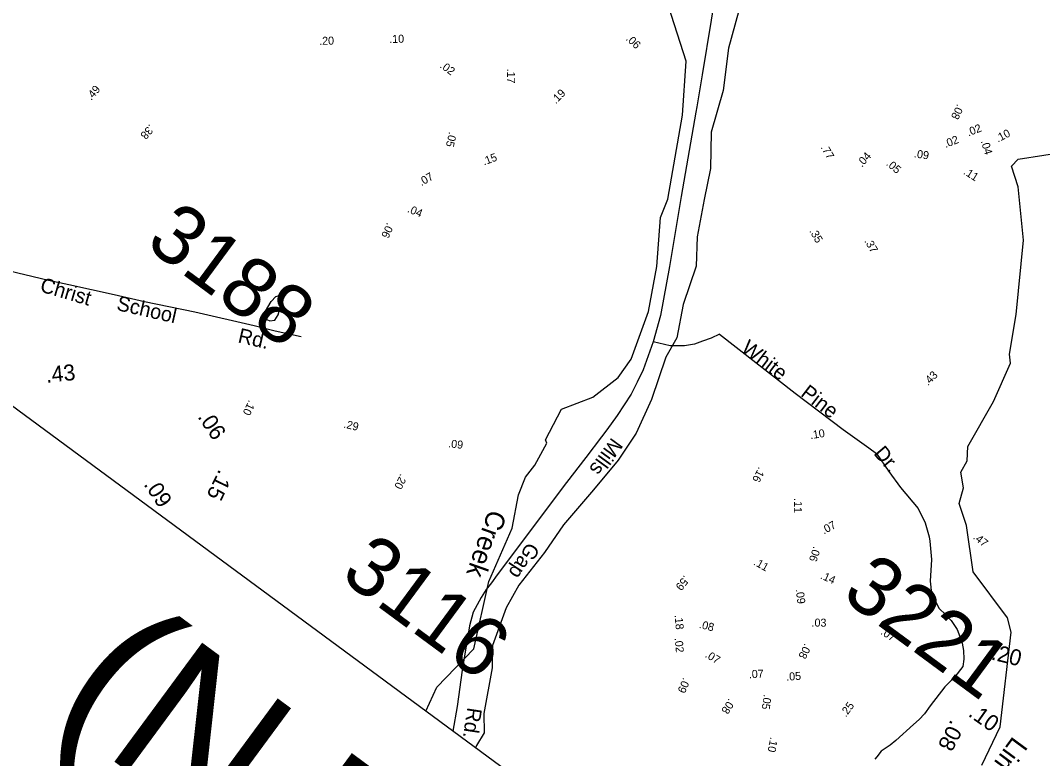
# Model space of a CAD drawing. Extents: x 945666 to 965748, y 644452 to 663300.
# Drawn here: x 953745 to 954782, y 657119 to 657868 of the extents above; entities that cross this region are included whole.
import ezdxf

# ---------------------------------------------------------------- set-up
doc = ezdxf.new("R2010")
doc.units = 0
for name, color, linetype in [('Exist Boundary Political Urban Extension UEB', 7, 'Continuous'), ('Exist Hydrographic Creek Single Shore', 7, 'Continuous'), ('Exist Hydrographic Pond Under 1500 Sq Ft', 7, 'Continuous'), ('Exist Road Secondary Mileage Tenths English Label', 7, 'Continuous'), ('Exist Road Secondary Type 51 Attributed', 7, 'Continuous'), ('Exist Road Secondary Type 51 Label', 7, 'Continuous'), ('Old_Level_1', 7, 'Continuous'), ('Old_Level_38', 7, 'Continuous'), ('Prop Paved Shoulder', 7, 'Continuous'), ('Sheet Data Field CELL', 7, 'Continuous'), ('Sheet Sticker Preliminary CELL', 7, 'Continuous')]:
    doc.layers.add(name, color=color, linetype=linetype)

msp = doc.modelspace()

# ---------------------------------------------------------------- linework, layer by layer
at = {"layer": 'Exist Boundary Political Urban Extension UEB'}
msp.add_lwpolyline([(954473.5, 657876.5), (954463.4, 657839.7), (954457.9, 657796.7), (954445.6, 657754.7), (954445, 657717.9), (954438.5, 657686.2), (954431.5, 657648.4), (954430.6, 657618.8), (954417.2, 657579.7), (954410.9, 657545.9), (954399.6, 657526.5), (954385.2, 657483.6), (954369.6, 657449.2), (954351.5, 657421.8), (954326.4, 657391.9), (954295.9, 657356.3), (954276.8, 657328.2), (954250.7, 657295.1), (954237.6, 657272.1), (954223.8, 657233.8), (954223.4, 657211.2), (954215, 657165.1), (954215.4, 657145.4), (954207.7, 657132.6), (954206.6, 657130.3)], dxfattribs=at)
at = {"layer": 'Exist Hydrographic Creek Single Shore'}
for points in [[(954294, 657473.7), (954325.7, 657485.8), (954351.3, 657505.9), (954364.5, 657524.3), (954382.1, 657572.6), (954390.5, 657618.2), (954394.2, 657668.1), (954401.8, 657686.5), (954416.8, 657771.7), (954420.3, 657826.6), (954402.3, 657882.3), (954402, 657897.6), (954413.5, 657952.2), (954415, 658020.4), (954407.9, 658060.3), (954408.9, 658084.2), (954421.5, 658112.4)], [(954720.4, 657112.4), (954738.9, 657151.4), (954750.2, 657247.6), (954746.3, 657261.9), (954711.5, 657308.6), (954704.7, 657355.7), (954697.4, 657378), (954701.8, 657394), (954699, 657409.6), (954705.5, 657421.2), (954706, 657435.9), (954732.3, 657481.3), (954749.4, 657520.3), (954748.5, 657529.6), (954755.3, 657569.5), (954762.6, 657645.1), (954757.2, 657699.2), (954750.3, 657720.1), (954757.3, 657727.2), (954809.4, 657735.5), (954828.6, 657742.2), (954855.2, 657763.7), (954881, 657794.4)], [(954156.3, 657167.4), (954167.5, 657191.8), (954205.1, 657230.7), (954220.2, 657298.7), (954243.9, 657353), (954250.1, 657386.9), (954257.2, 657404.6), (954266.7, 657416.7), (954278.9, 657439), (954277.7, 657442.7), (954294, 657473.7)]]:
    msp.add_lwpolyline(points, dxfattribs=at)
at = {"layer": 'Exist Hydrographic Pond Under 1500 Sq Ft'}
for points in [[(953995, 657564.6), (953992.4, 657567.2), (953993.6, 657572.9), (953999.3, 657583), (954003.9, 657588), (954006.4, 657588.6)], [(953995, 657564.6), (953998.1, 657563.4), (954003.2, 657564), (954006.4, 657569.4), (954009, 657579.3), (954008.1, 657586.6), (954006.4, 657588.6)]]:
    msp.add_lwpolyline(points, dxfattribs=at)
at = {"layer": 'Exist Road Secondary Type 51 Attributed'}
for points in [[(954478.9, 658294.7), (954479.7, 658288), (954481.3, 658279.9), (954484, 658254.2), (954489, 658198.6), (954489.7, 658177.4), (954484.8, 658097), (954478.2, 658046.7), (954465.5, 657985.8), (954461.3, 657964.9), (954445.7, 657868.2), (954436.6, 657812.8), (954431.3, 657780.2), (954430.3, 657774.8)], [(954430.3, 657774.8), (954415.4, 657689.2), (954403.4, 657618.4), (954394.4, 657568.7), (954386.9, 657542.1)], [(953550.1, 657617.9), (953647.7, 657623.1), (953683.5, 657623.9), (953695.4, 657622.6), (953702.8, 657621.1), (953709.6, 657619.6), (953773.6, 657604.5), (953793.9, 657600), (953840.1, 657589.8)], [(953840.1, 657589.8), (953870.8, 657582.8), (953921.8, 657572.3), (953982, 657558.4), (954003.3, 657553.2), (954029.7, 657547.2)], [(954386.9, 657542.1), (954376.8, 657513.4), (954370.8, 657500.9), (954364.6, 657488.9), (954350.2, 657467.3), (954339.8, 657452.7), (954334.6, 657445.7)], [(954454.2, 657549.6), (954445.7, 657545.6), (954436.9, 657542.6), (954428.7, 657539.5), (954418.6, 657537.9), (954404.3, 657538), (954386.9, 657542.1)], [(954454.2, 657549.6), (954530.9, 657489.8), (954579.8, 657453), (954605.7, 657434.6), (954613.6, 657428.6), (954626, 657410.3), (954637.9, 657394.3), (954655.8, 657372.8), (954662.8, 657358.3), (954666.9, 657344.3), (954667.5, 657339.8), (954667.9, 657336.2)], [(954334.6, 657445.7), (954318.7, 657424.6), (954298.8, 657399.2), (954228.6, 657305.6), (954222.9, 657297.6), (954217.6, 657290.8), (954212.3, 657282.6), (954204.4, 657267.8), (954200.4, 657253.8), (954193.2, 657209), (954188, 657172.1), (954183.7, 657147.2)], [(954667.9, 657336.2), (954669.1, 657321.2), (954667.9, 657299.3), (954669.3, 657286.6), (954673.6, 657278), (954677.2, 657271.6), (954683.4, 657265.4), (954689.3, 657259.2), (954695.3, 657250.1), (954698.1, 657243.2), (954700.3, 657236.2), (954701.6, 657228.9), (954702.2, 657220.1), (954700.9, 657212.6), (954692.9, 657202.1), (954682.9, 657192.1), (954667.9, 657172.9), (954662.3, 657164.7), (954656.9, 657158.9), (954650.9, 657153.7), (954633.1, 657137.6), (954627.4, 657132.8), (954618.3, 657126.8), (954613.7, 657120.9), (954611.7, 657118.8)]]:
    msp.add_lwpolyline(points, dxfattribs=at)
at = {"layer": 'Old_Level_1'}
for points in [[(953667.4, 661172.9), (956829.7, 658840.6), (955088.6, 656479.8), (951926.2, 658812.1)], [(951728.9, 658544.5), (954891.3, 656212.2), (955088.6, 656479.8), (951926.2, 658812.1)]]:
    msp.add_lwpolyline(points, close=True, dxfattribs=at)

# ---------------------------------------------------------------- texts
at = {"layer": 'Exist Road Secondary Mileage Tenths English Label'}
for s, height, rotation, p in [('.10', 8.12, 1.4921, (954119.2, 657845)), ('.20', 8.12, 1.3752, (954048.1, 657843.1)), ('.06', 8.12, 316.6563, (954358.6, 657848.7)), ('.02', 8.12, 323.6552, (954169.9, 657820.7)), ('.17', 8.12, 269.8536, (954238.7, 657819.1)), ('.49', 8.12, 49.1814, (953816.8, 657786.3)), ('.19', 8.12, 45.38, (954288.1, 657782.7)), ('.08', 8.12, 243.6353, (954695.5, 657783.6)), ('.38', 8.12, 228.3123, (953876.1, 657763.2)), ('.02', 8.12, 21.4305, (954706.8, 657750.2)), ('.05', 8.12, 256.9305, (954179.9, 657755.3)), ('.02', 8.12, 21.4305, (954683.6, 657738.5)), ('.10', 8.12, 27.4444, (954736.7, 657744)), ('.77', 8.12, 300.1192, (954556.5, 657739.2)), ('.04', 8.12, 286.8981, (954719.2, 657745.4)), ('.15', 8.12, 21.0543, (954215.3, 657720.7)), ('.04', 8.12, 48.7257, (954598.7, 657718.6)), ('.09', 8.12, 350.9458, (954651.1, 657729.2)), ('.05', 8.12, 319.4635, (954622.6, 657721.7)), ('.07', 8.12, 30.5483, (954151.8, 657699.7)), ('.11', 8.12, 327.6078, (954701, 657712.6)), ('.04', 8.12, 337.2713, (954136.9, 657673.8)), ('.06', 8.12, 245.2099, (954117.1, 657663.3)), ('.35', 8.12, 300.1192, (954545, 657654.4)), ('.37', 8.12, 300.1192, (954600.9, 657644.2)), ('.43', 16.24, 5.7989, (953771.3, 657500.3)), ('.43', 8.12, 45.38, (954665.7, 657496.8)), ('.10', 8.12, 244.1519, (953976.8, 657483.4)), ('.06', 16.24, 303.7208, (953924.2, 657465.9)), ('.29', 8.12, 347.0032, (954072.3, 657455)), ('.09', 8.12, 353.7368, (954178.6, 657435)), ('.15', 16.24, 244.1519, (953946.6, 657413.3)), ('.20', 8.12, 244.0535, (954130.6, 657408.6)), ('.16', 8.12, 242.6273, (954494.1, 657415.5)), ('.09', 16.24, 303.7208, (953869.5, 657397.3)), ('.11', 8.12, 269.6042, (954529.8, 657383.4)), ('.07', 8.12, 28.4014, (954560.1, 657346.5)), ('.47', 8.12, 320.8738, (954710.8, 657342.7)), ('.06', 8.12, 251.4292, (954549.6, 657335)), ('.11', 8.12, 330.7195, (954488.1, 657316.2)), ('.59', 8.12, 231.4865, (954418.5, 657305.7)), ('.14', 8.12, 336.1258, (954555.8, 657302.1)), ('.09', 8.12, 277.303, (954531.5, 657290.7)), ('.18', 8.12, 275.2098, (954408.6, 657264.8)), ('.03', 8.12, 359.1426, (954547.5, 657253.2)), ('.08', 8.12, 345.7745, (954432.9, 657251.9)), ('.02', 8.12, 275.2098, (954408.7, 657241.4)), ('.07', 8.12, 326.7724, (954617, 657245.9)), ('.08', 8.12, 243.7107, (954540.7, 657236.5)), ('.20', 16.24, 346.2139, (954729, 657219.9)), ('.07', 8.12, 328.9496, (954438.9, 657222.6)), ('.07', 8.12, 2.7959, (954484.1, 657200.7)), ('.09', 8.12, 246.3885, (954417.5, 657201.8)), ('.05', 8.12, 3.8424, (954522.1, 657198.2)), ('.08', 8.12, 237.4031, (954463.8, 657180.6)), ('.05', 8.12, 261.3374, (954499.2, 657184.6)), ('.25', 8.12, 53.5909, (954582.4, 657160.8)), ('.10', 16.24, 324.8227, (954705.6, 657163)), ('.08', 16.24, 242.8172, (954689.1, 657159.4)), ('.10', 8.12, 258.4988, (954505.9, 657141.4))]:
    msp.add_text(s, height=height, rotation=rotation, dxfattribs=at).set_placement(p)
at = {"layer": 'Exist Road Secondary Type 51 Label'}
for s, rotation, p in [('Christ', 343.6946, (953763.9, 657593.2)), ('School', 347.1566, (953841.7, 657574.3)), ('Rd.', 347.0032, (953964.8, 657541.5)), ('White', 322.4026, (954475.2, 657533.2)), ('Pine', 322.4026, (954535.6, 657487.8)), ('Mills', 233.9145, (954345, 657445.6)), ('Dr.', 310.1836, (954609.9, 657428.5)), ('Gap', 236.7725, (954260.2, 657339.6)), ('Rd.', 261.3363, (954198.5, 657171.7))]:
    msp.add_text(s, height=15, rotation=rotation, dxfattribs=at).set_placement(p)
at = {"layer": 'Old_Level_1'}
for s, p in [('3188', (953870.2, 657639.3)), ('3116', (954068, 657302.6)), ('3221', (954576.5, 657282.8))]:
    msp.add_text(s, height=60, rotation=323.5908, dxfattribs=at).set_placement(p)
at = {"layer": 'Old_Level_38'}
msp.add_text('(N.T.S)', height=150, rotation=323.5908, dxfattribs=at).set_placement((953773.3, 657165.5))
at = {"layer": 'Prop Paved Shoulder'}
for s, rotation, p in [('Creek', 250.5216, (954220.3, 657372.8)), ('Limestone', 233.6808, (954752.1, 657142.6))]:
    msp.add_text(s, height=19.49, rotation=rotation, dxfattribs=at).set_placement(p)
at = {"layer": 'Sheet Data Field CELL'}
for s, p in [('1. DESIGN EXCEPTIONS FOR VERTICAL CURVE K VALUE', (951636, 658446)), (' AND STOPPING SIGHT DISTANCE HAVE BEEN REQUESTED', (951567.9, 658353.7))]:
    msp.add_text(s, height=87.501, rotation=323.5908, dxfattribs=at).set_placement(p)
at = {"layer": 'Sheet Sticker Preliminary CELL'}
msp.add_text('.10', height=8.12, rotation=9.0782, dxfattribs=at).set_placement((954546.6, 657443.2))

doc.saveas('drawing.dxf')
